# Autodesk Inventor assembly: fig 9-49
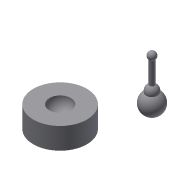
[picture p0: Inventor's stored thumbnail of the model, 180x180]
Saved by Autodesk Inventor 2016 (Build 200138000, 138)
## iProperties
Created: 2013-07
Part Number: fig 9-49
Document SubType Name: Assembly
Designer: CADCIM
Author: CADCIM
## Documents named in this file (3)
- D:\KAVITA\Autodesk Inventor_ 2016 Project_Kavita\Inventor_Part Files\Inventor_2016_Part\c09_Inv_2016\c09_inv_2016_prt\fig 9-49.iam
- D:\KAVITA\Autodesk Inventor_ 2016 Project_Kavita\Inventor_Part Files\Inventor_2016_Part\c09_Inv_2016\c09_inv_2016_prt\19.ipt
- D:\KAVITA\Autodesk Inventor_ 2016 Project_Kavita\Inventor_Part Files\Inventor_2016_Part\c09_Inv_2016\c09_inv_2016_prt\20.ipt
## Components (2 placed, 2 different names)
1. 19:1
2. 20:2
